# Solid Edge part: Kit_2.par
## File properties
Sűrűség: 0,000 kg/m^3
Pontosság: 0,990
Author: bmolnar
Last saved by: bmolnar
Revision: 78
Username: bmolnar
Dokumentum tartalom típus: 0
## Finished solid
Body 1: solid body, 21 faces, 37 edges, 18 vertices.
  Faces by surface: cylinder 10, plane 9, cone 1, torus 1
  Edges by curve: circle 23, line 14
Bounding box of the edges (mm; curved faces can reach further): 68.000 x 67.800 x 6.000, from (-34, -32.35, 1.35) to (34, 35.45, 7.35).
Cylindrical faces by radius (mm): R1.5 x2, R3 x4, R23.5 x1, R29.65 x1, R32.35 x1, R34 x1
Conical faces (half-angle, radius in mm at the cone's reference point): 45 deg R23 x1
Toroidal faces (ring radius, tube radius in mm): R24.3 r0.8 x1
Planar faces by outward normal: +z 2, -z 5, oblique 2
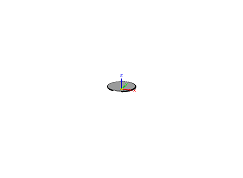
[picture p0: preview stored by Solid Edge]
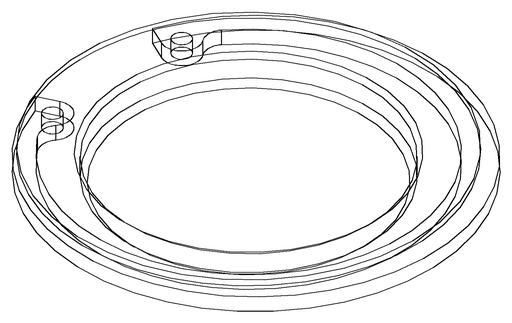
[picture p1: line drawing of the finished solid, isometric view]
